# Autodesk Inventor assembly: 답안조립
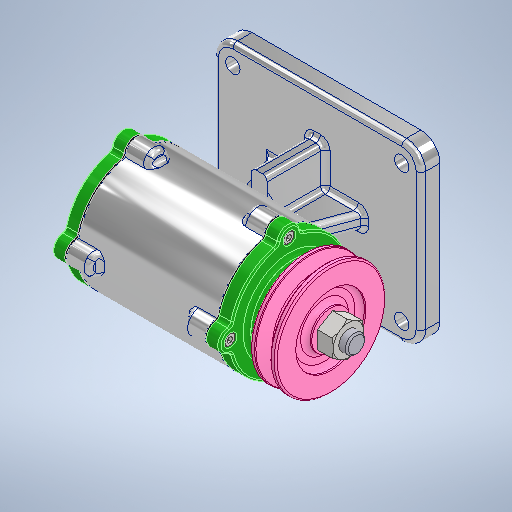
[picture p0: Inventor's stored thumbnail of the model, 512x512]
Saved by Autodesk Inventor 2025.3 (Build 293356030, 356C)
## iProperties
Created: 2025-08
Part Number: 답안조립
Document SubType Name: Assembly
Designer: infra011
Author: infra011
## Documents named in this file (12)
- C:\Users\infra011\Desktop\750806V1013\답안조립.iam
- C:\Users\infra011\Desktop\750806V1013\V-벨트풀리\V-벨트풀리.ipt
- C:\Users\infra011\Desktop\750806V1013\개스킷\개스킷.ipt
- C:\Users\infra011\Desktop\750806V1013\너트 M12 x 1.25\너트 M12 x 1.25.ipt
- C:\Users\infra011\Desktop\750806V1013\뒤커버\뒤커버.ipt
- C:\Users\infra011\Desktop\750806V1013\베어링 6204\베어링 6204.ipt
- C:\Users\infra011\Desktop\750806V1013\볼트 M4 x 12\볼트 M4 x 12.ipt
- C:\Users\infra011\Desktop\750806V1013\앞커버\앞커버.ipt
- C:\Users\infra011\Desktop\750806V1013\오일 실\오일 실.ipt
- C:\Users\infra011\Desktop\750806V1013\축\축.ipt
- C:\Users\infra011\Desktop\750806V1013\키 4 x 4\키 4 x 4.ipt
- C:\Users\infra011\Desktop\750806V1013\본체.ipt
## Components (3 placed, 2 different names)
1. V-벨트풀리:1
2. 개스킷:1
3. 개스킷:2
